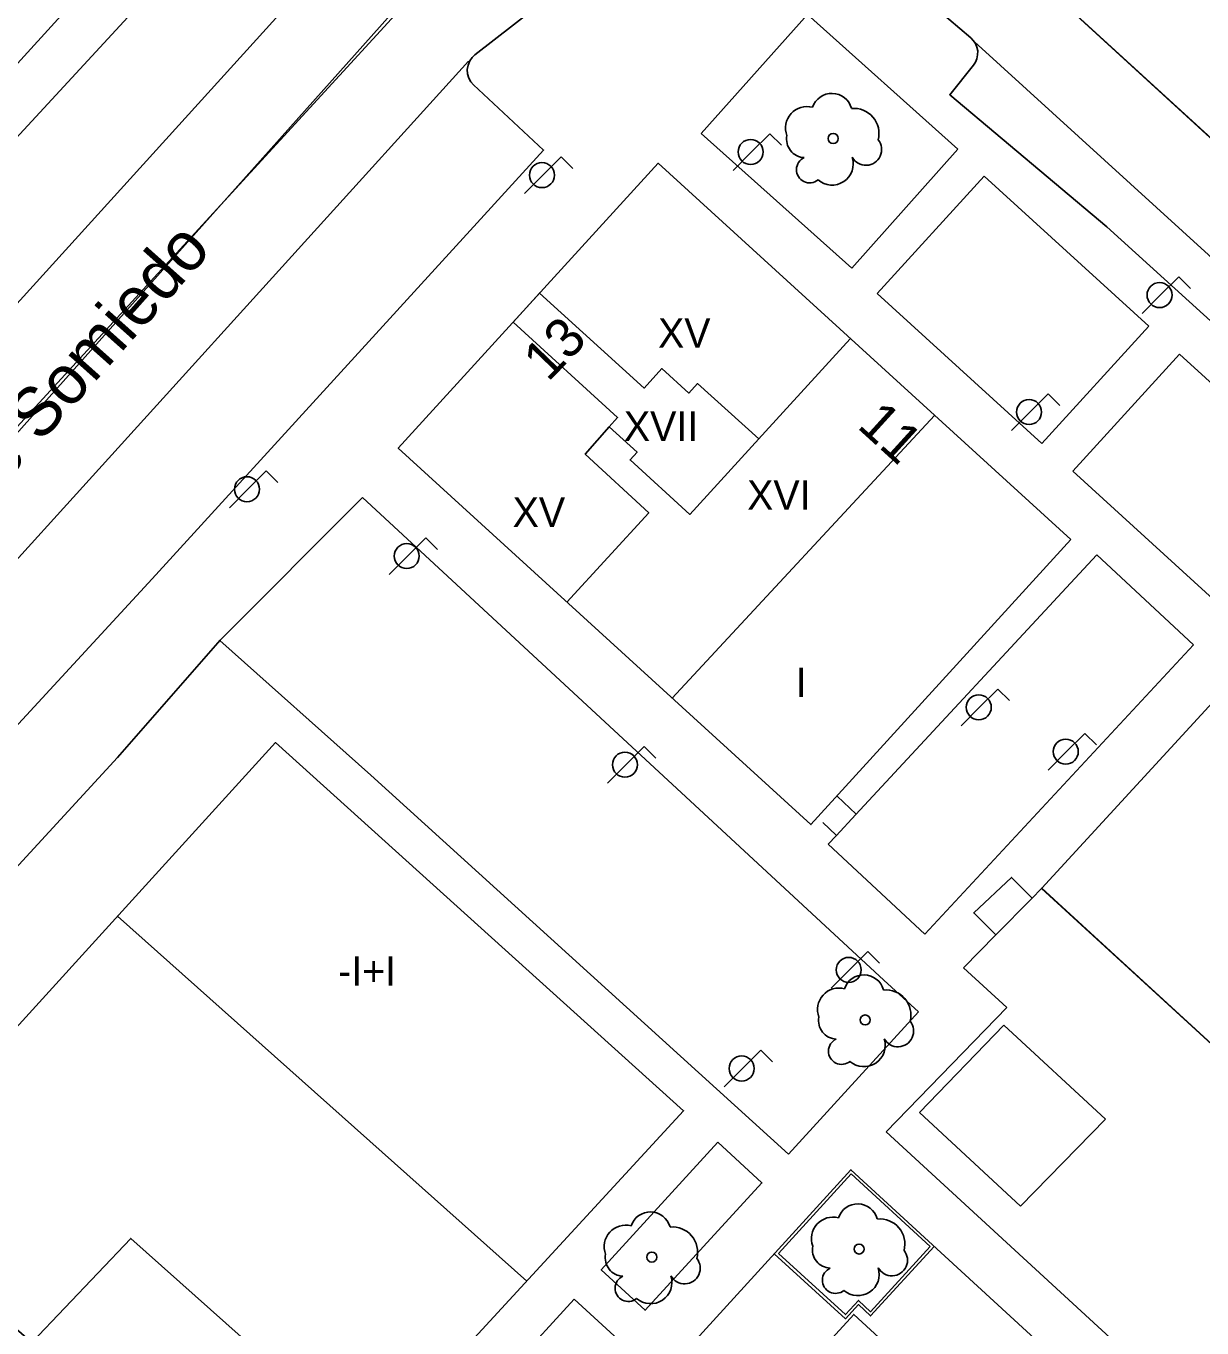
# Model space of a CAD drawing. Extents: x 282771 to 285132, y 4823109 to 4825496.
# Drawn here: x 283795 to 283854.9, y 4823323.1 to 4823389.4 of the extents above; entities that cross this region are included whole.
import ezdxf

# ---------------------------------------------------------------- set-up
doc = ezdxf.new("R2010")
doc.units = 0
for name, color, linetype in [('ACERA-BORDILLO', 7, 'Continuous'), ('ACERA-INTERIOR', 7, 'Continuous'), ('ARBOL', 7, 'Continuous'), ('BORDILLO', 7, 'Continuous'), ('CALLE-EJE', 7, 'Continuous'), ('CALLE-TEXTO', 7, 'Continuous'), ('EDIFICIO', 7, 'Continuous'), ('FAROLA', 7, 'Continuous'), ('MEDIANERA', 7, 'Continuous'), ('NUM-LOCAL', 7, 'Continuous'), ('NUM-PORTAL', 7, 'Continuous'), ('SENAL-VIARIA', 7, 'Continuous'), ('TXT-ALTURA-EDIFICIO', 7, 'Continuous'), ('ZONA-VERDE', 7, 'Continuous')]:
    doc.layers.add(name, color=color, linetype=linetype)

msp = doc.modelspace()

# ---------------------------------------------------------------- linework, layer by layer
at = {"layer": 'ACERA-BORDILLO'}
for points in [[(283785.072, 4823373.561), (283808.693, 4823399.156), (283812.812, 4823395.481), (283835.171, 4823420.3), (283839.411, 4823425.06), (283835.471, 4823428.73), (283863.261, 4823458.42), (283888.661, 4823486.42)], [(283778.138, 4823336.071), (283801.402, 4823361.271), (283821.341, 4823383.111), (283817.768, 4823386.439), (283817.638, 4823386.588), (283817.533, 4823386.773), (283817.467, 4823386.987), (283817.451, 4823387.215), (283817.487, 4823387.442), (283817.572, 4823387.649), (283817.693, 4823387.824), (283817.836, 4823387.96), (283821.935, 4823391.148)], [(283840.857, 4823390.736), (283843.105, 4823388.825), (283843.231, 4823388.696), (283843.337, 4823388.538), (283843.414, 4823388.356), (283843.453, 4823388.158), (283843.452, 4823387.956), (283843.412, 4823387.763), (283843.338, 4823387.588), (283843.238, 4823387.438), (283842.031, 4823385.931), (283850.031, 4823379.191), (283891.081, 4823341.981)], [(283874.871, 4823296.362), (283836.991, 4823331.161), (283804.532, 4823295.562)]]:
    msp.add_lwpolyline(points, dxfattribs=at)
at = {"layer": 'ACERA-INTERIOR'}
for points in [[(283804.862, 4823358.141), (283799.632, 4823352.161), (283778.152, 4823328.811)], [(283836.289, 4823350.198), (283837.261, 4823349.281)], [(283835.561, 4823348.851), (283836.251, 4823348.201)], [(283846.221, 4823345.001), (283845.171, 4823346.051), (283843.251, 4823344.241), (283844.371, 4823343.131)]]:
    msp.add_lwpolyline(points, dxfattribs=at)
at = {"layer": 'ARBOL'}
for centre in [(283836.091, 4823383.701), (283837.721, 4823338.791), (283837.411, 4823327.121), (283826.851, 4823326.711)]:
    msp.add_circle(centre, 0.255, dxfattribs=at)
for centre, radius, start, end in [((283836.021, 4823384.961), 1.038, 15.64228, 161.38435), ((283834.761, 4823384.231), 1.097, 75.4318, 200.55608), ((283837.151, 4823383.961), 1.272, 345.03273, 95.79925), ((283834.651, 4823383.661), 0.935, 168.59898, 268.13236), ((283837.761, 4823383.131), 0.797, 208.96246, 38.99103), ((283834.891, 4823382.111), 0.672, 113.73672, 309.4725), ((283836.031, 4823382.411), 1.086, 228.95447, 17.92796), ((283837.651, 4823340.051), 1.038, 15.64228, 161.38435), ((283836.391, 4823339.321), 1.097, 75.4318, 200.55608), ((283838.781, 4823339.051), 1.272, 345.03273, 95.79925), ((283836.281, 4823338.751), 0.935, 168.59898, 268.13236), ((283839.391, 4823338.221), 0.797, 208.96246, 38.99103), ((283836.521, 4823337.201), 0.672, 113.73672, 309.4725), ((283837.661, 4823337.501), 1.086, 228.95447, 17.92796), ((283837.341, 4823328.381), 1.038, 15.64228, 161.38435), ((283826.781, 4823327.971), 1.038, 15.64228, 161.38435), ((283836.081, 4823327.651), 1.097, 75.4318, 200.55608), ((283838.471, 4823327.381), 1.272, 345.03273, 95.79925), ((283825.521, 4823327.241), 1.097, 75.4318, 200.55608), ((283827.911, 4823326.971), 1.272, 345.03273, 95.79925), ((283835.971, 4823327.081), 0.935, 168.59898, 268.13236), ((283839.081, 4823326.551), 0.797, 208.96246, 38.99103), ((283825.411, 4823326.671), 0.935, 168.59898, 268.13236), ((283828.521, 4823326.141), 0.797, 208.96246, 38.99103), ((283825.651, 4823325.121), 0.672, 113.73672, 309.4725), ((283826.791, 4823325.421), 1.086, 228.95447, 17.92796), ((283836.211, 4823325.531), 0.672, 113.73672, 309.4725), ((283837.351, 4823325.831), 1.086, 228.95447, 17.92796)]:
    msp.add_arc(centre, radius, start, end, dxfattribs=at)
at = {"layer": 'BORDILLO'}
msp.add_lwpolyline([(283841.241, 4823327.241), (283838.001, 4823323.711), (283837.381, 4823324.291), (283836.721, 4823323.571), (283833.081, 4823326.881)], dxfattribs=at)
at = {"layer": 'CALLE-EJE'}
for points in [[(283829.231, 4823407.601), (283749.482, 4823318.271)], [(283918.081, 4823326.402), (283829.231, 4823407.601)]]:
    msp.add_lwpolyline(points, dxfattribs=at)
at = {"layer": 'EDIFICIO'}
for points in [[(283848.201, 4823363.261), (283834.961, 4823348.741), (283813.932, 4823367.921), (283827.171, 4823382.441), (283848.201, 4823363.261)], [(283884.491, 4823330.371), (283891.081, 4823324.361), (283896.151, 4823319.742), (283891.081, 4823314.242), (283886.401, 4823309.162), (283874.891, 4823319.692), (283872.341, 4823316.882), (283868.521, 4823320.371), (283869.451, 4823321.391), (283860.411, 4823329.621), (283859.521, 4823328.641), (283855.531, 4823332.251), (283858.071, 4823335.101), (283846.721, 4823345.511), (283856.381, 4823356.021), (283867.911, 4823345.491), (283884.491, 4823330.371)], [(283794.742, 4823322.821), (283786.622, 4823329.771), (283807.672, 4823352.921), (283828.471, 4823334.161), (283812.492, 4823316.801), (283814.692, 4823314.772), (283800.912, 4823299.832), (283786.542, 4823312.892), (283795.272, 4823322.351), (283794.742, 4823322.821)]]:
    msp.add_lwpolyline(points, dxfattribs=at)
at = {"layer": 'FAROLA'}
for p, q in [((283832.865, 4823383.943), (283831.925, 4823383.013)), ((283833.455, 4823383.353), (283832.865, 4823383.943)), ((283831.925, 4823383.013), (283830.995, 4823382.073)), ((283822.235, 4823382.762), (283821.295, 4823381.832)), ((283822.825, 4823382.172), (283822.235, 4823382.762)), ((283821.295, 4823381.832), (283820.365, 4823380.892)), ((283853.698, 4823376.65), (283852.758, 4823375.72)), ((283854.288, 4823376.06), (283853.698, 4823376.65)), ((283852.758, 4823375.72), (283851.828, 4823374.78)), ((283847.051, 4823370.693), (283846.111, 4823369.763)), ((283847.641, 4823370.103), (283847.051, 4823370.693)), ((283846.111, 4823369.763), (283845.181, 4823368.823)), ((283807.205, 4823366.759), (283806.265, 4823365.829)), ((283807.795, 4823366.169), (283807.205, 4823366.759)), ((283806.265, 4823365.829), (283805.335, 4823364.889)), ((283815.344, 4823363.356), (283814.404, 4823362.426)), ((283815.934, 4823362.766), (283815.344, 4823363.356)), ((283814.404, 4823362.426), (283813.474, 4823361.486)), ((283844.488, 4823355.649), (283843.548, 4823354.719)), ((283845.078, 4823355.059), (283844.488, 4823355.649)), ((283843.548, 4823354.719), (283842.618, 4823353.779)), ((283848.921, 4823353.391), (283847.981, 4823352.461)), ((283849.511, 4823352.801), (283848.921, 4823353.391)), ((283826.462, 4823352.726), (283825.522, 4823351.796)), ((283827.052, 4823352.136), (283826.462, 4823352.726)), ((283847.981, 4823352.461), (283847.051, 4823351.521)), ((283825.522, 4823351.796), (283824.592, 4823350.856)), ((283837.862, 4823342.273), (283836.922, 4823341.343)), ((283838.452, 4823341.683), (283837.862, 4823342.273)), ((283836.922, 4823341.343), (283835.992, 4823340.403)), ((283832.407, 4823337.247), (283831.467, 4823336.317)), ((283832.997, 4823336.657), (283832.407, 4823337.247)), ((283831.467, 4823336.317), (283830.537, 4823335.377))]:
    msp.add_line(p, q, dxfattribs=at)
for centre, radius in [((283831.885, 4823383.013), 0.638), ((283821.255, 4823381.832), 0.637), ((283852.718, 4823375.72), 0.637), ((283846.071, 4823369.763), 0.638), ((283806.225, 4823365.829), 0.638), ((283814.364, 4823362.426), 0.637), ((283843.508, 4823354.719), 0.637), ((283847.941, 4823352.461), 0.637), ((283825.482, 4823351.796), 0.637), ((283836.882, 4823341.343), 0.637), ((283831.427, 4823336.317), 0.638)]:
    msp.add_circle(centre, radius, dxfattribs=at)
at = {"layer": 'MEDIANERA'}
for points in [[(283824.681, 4823369.011), (283825.111, 4823369.481), (283819.781, 4823374.341), (283821.121, 4823375.821), (283826.461, 4823370.981), (283827.361, 4823371.981), (283828.741, 4823370.731), (283829.171, 4823371.211), (283832.301, 4823368.391)], [(283832.291, 4823368.381), (283836.961, 4823373.501)], [(283841.261, 4823369.591), (283827.881, 4823355.191)], [(283824.681, 4823369.011), (283823.461, 4823367.611), (283826.691, 4823364.631), (283822.521, 4823360.071)], [(283832.301, 4823368.391), (283828.781, 4823364.551), (283825.741, 4823367.321), (283826.101, 4823367.711), (283824.681, 4823369.011)], [(283799.622, 4823344.071), (283820.482, 4823325.481)], [(283795.272, 4823322.351), (283800.302, 4823327.661), (283812.492, 4823316.801)]]:
    msp.add_lwpolyline(points, dxfattribs=at)
at = {"layer": 'SENAL-VIARIA'}
for points in [[(283767.615, 4823345.637), (283812.811, 4823395.481)], [(283770.876, 4823343.271), (283815.658, 4823392.071)], [(283846.291, 4823391.979), (283899.822, 4823342.997)], [(283898.931, 4823337.981), (283843.284, 4823388.617)], [(283774.097, 4823339.745), (283817.518, 4823387.631)], [(283871.096, 4823292.558), (283837.136, 4823323.785), (283792.822, 4823275.372)]]:
    msp.add_lwpolyline(points, dxfattribs=at)
at = {"layer": 'ZONA-VERDE'}
for p, q in [((283806.549, 4823400.689), (283782.673, 4823374.56)), ((283829.369, 4823383.96), (283834.779, 4823390.01)), ((283834.779, 4823390.01), (283842.449, 4823383.15)), ((283837.039, 4823377.1), (283829.369, 4823383.96)), ((283842.449, 4823383.15), (283837.039, 4823377.1)), ((283838.329, 4823375.8), (283843.779, 4823381.78)), ((283843.779, 4823381.78), (283852.169, 4823374.14)), ((283846.719, 4823368.16), (283838.329, 4823375.8)), ((283852.169, 4823374.14), (283846.719, 4823368.16)), ((283848.299, 4823366.75), (283853.729, 4823372.71)), ((283853.729, 4823372.71), (283861.459, 4823365.67)), ((283856.029, 4823359.71), (283848.299, 4823366.75)), ((283804.849, 4823358.119), (283812.109, 4823365.409)), ((283812.109, 4823365.409), (283816.899, 4823360.969)), ((283837.249, 4823349.26), (283849.279, 4823362.23)), ((283849.279, 4823362.23), (283849.519, 4823362.48)), ((283849.519, 4823362.48), (283854.449, 4823357.91)), ((283816.899, 4823360.969), (283838.679, 4823340.82)), ((283812.529, 4823351.259), (283804.849, 4823358.119)), ((283854.449, 4823357.91), (283840.769, 4823343.17)), ((283833.809, 4823331.959), (283812.529, 4823351.259)), ((283836.243, 4823348.176), (283837.249, 4823349.26)), ((283835.839, 4823347.74), (283836.243, 4823348.176)), ((283840.769, 4823343.17), (283835.839, 4823347.74)), ((283844.361, 4823343.107), (283846.208, 4823344.98)), ((283846.208, 4823344.98), (283846.709, 4823345.49)), ((283846.709, 4823345.49), (283858.059, 4823335.08)), ((283842.729, 4823341.45), (283844.361, 4823343.107)), ((283844.939, 4823339.43), (283842.729, 4823341.45)), ((283838.679, 4823340.82), (283840.439, 4823339.2)), ((283840.439, 4823339.2), (283833.809, 4823331.959)), ((283838.789, 4823333.089), (283844.939, 4823339.43)), ((283840.489, 4823334.079), (283844.789, 4823338.52)), ((283844.789, 4823338.52), (283849.969, 4823333.74)), ((283845.639, 4823329.299), (283840.489, 4823334.079)), ((283849.969, 4823333.74), (283845.639, 4823329.299)), ((283850.627, 4823322.199), (283838.789, 4823333.089)), ((283837.001, 4823330.949), (283833.298, 4823326.888)), ((283841.037, 4823327.241), (283837.001, 4823330.949))]:
    msp.add_line(p, q, dxfattribs=at)
for points in [[(283830.211, 4823332.561), (283824.271, 4823326.063), (283826.511, 4823324.001), (283832.461, 4823330.491), (283830.211, 4823332.561)], [(283833.298, 4823326.888), (283836.712, 4823323.783), (283837.373, 4823324.504), (283837.993, 4823323.924), (283841.037, 4823327.241)], [(283822.903, 4823324.566), (283816.75, 4823317.835), (283818.982, 4823315.782), (283825.141, 4823322.511), (283822.903, 4823324.566)]]:
    msp.add_lwpolyline(points, dxfattribs=at)

# ---------------------------------------------------------------- texts
at = {"layer": 'CALLE-TEXTO'}
msp.add_text('Calle Puerto de Somiedo', height=2.5, rotation=48.24292, dxfattribs=at).set_placement((283779.724, 4823350.269))
at = {"layer": 'NUM-LOCAL'}
msp.add_text('13', height=2, rotation=46.03004, dxfattribs=at).set_placement((283821.566, 4823371.258))
at = {"layer": 'NUM-PORTAL'}
msp.add_text('11', height=2, rotation=317.68004, dxfattribs=at).set_placement((283837.259, 4823368.995))
at = {"layer": 'TXT-ALTURA-EDIFICIO'}
for s, p in [('XV', (283827.168, 4823373.041)), ('XVII', (283825.427, 4823368.291)), ('XVI', (283831.707, 4823364.781)), ('XV', (283819.758, 4823363.911)), ('I', (283834.18, 4823355.241)), ('-I+I', (283810.868, 4823340.531))]:
    msp.add_text(s, height=1.5, rotation=0.00004, dxfattribs=at).set_placement(p)

doc.saveas('drawing.dxf')
